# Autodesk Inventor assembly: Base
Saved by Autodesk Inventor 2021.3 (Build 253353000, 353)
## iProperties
Created: 2022-04
Part Number: Base
Document SubType Name: Assembly
Designer: Administrator
Title: Base v10
Author: Administrator
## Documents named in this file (2)
- c:\worker\convert-fusion-r02\tmp\job-1\57\output\files\f9e42cba-e390-44b0-9630-f24d5638462a\Base v10.iam
- c:\worker\convert-fusion-r02\tmp\job-1\57\output\files\f9e42cba-e390-44b0-9630-f24d5638462a\Component4.ipt
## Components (1 placed, 1 different names)
1. Component4:1
